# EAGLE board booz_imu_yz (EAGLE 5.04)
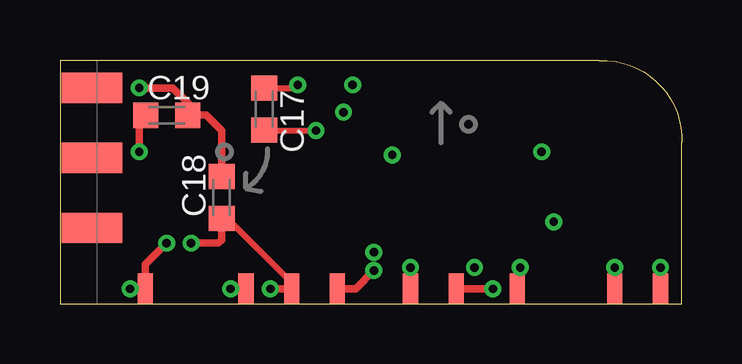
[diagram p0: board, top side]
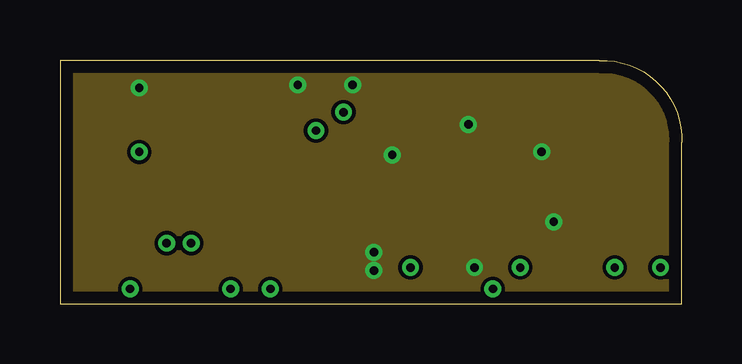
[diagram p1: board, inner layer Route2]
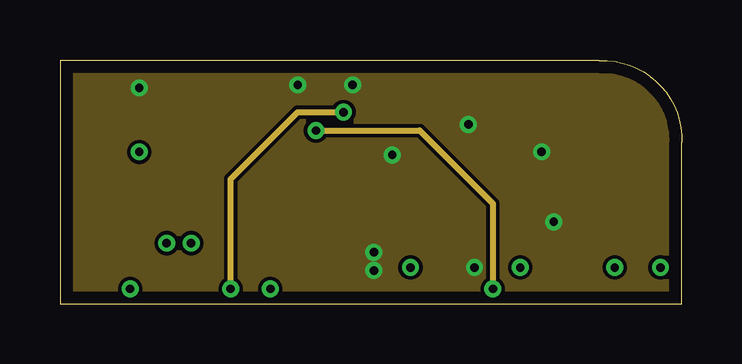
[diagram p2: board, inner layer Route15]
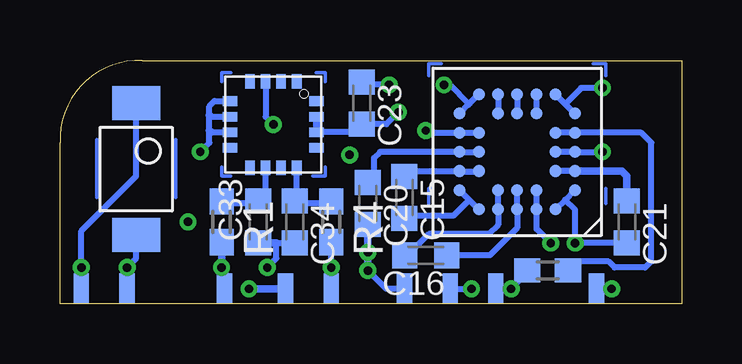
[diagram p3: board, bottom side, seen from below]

Size 25.91 x 10.16 mm. Coordinates in mm from the lower left corner, seen from the top.
Outline: 0,0 25.91,0 25.91,6.73 arc95 22.48,10.16 0,10.16 0,0
Copper layers (1*2+15*16): Top 0.035mm / dielectric 0.2mm / Route2 0.035mm / dielectric 1.5mm / Route15 0.035mm / dielectric 0.2mm / Bottom 0.035mm
Design rules "eurocircuits_verified_4l": minimum track width 0.15mm, minimum drill 0.35mm, track to track 0.15mm, track to pad 0.15mm, pad to pad 0.15mm, via to via 0.15mm, smd to smd 0.15mm, copper to edge 20mil, drill to drill 8mil, minimum pad ring 0.177mm, minimum via ring 0.177mm, stop-mask expansion 4mil, vias tented up to drill 14mil, thermal gap 10mil

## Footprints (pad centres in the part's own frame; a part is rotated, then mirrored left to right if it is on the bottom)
C0603K = smd 1.05 x 1.08: 1 -0.875,0; 2 0.875,0
BC-32 = smd 0.5 x 0.5: A2 -1.6,2.4; A3 -0.8,2.4; A4 0,2.4; A5 0.8,2.4; A6 1.6,2.4; B1 -2.4,1.6; B3 -0.8,1.6; B4 0,1.6; B5 0.8,1.6; B7 2.4,1.6; C1 -2.4,0.8; C2 -1.6,0.8; C6 1.6,0.8; C7 2.4,0.8; D1 -2.4,0; D2 -1.6,0; D6 1.6,0; D7 2.4,0; E1 -2.4,-0.8; E2 -1.6,-0.8; E6 1.6,-0.8; E7 2.4,-0.8; F1 -2.4,-1.6; F3 -0.8,-1.6; F4 0,-1.6; F5 0.8,-1.6; F7 2.4,-1.6; G2 -1.6,-2.4; G3 -0.8,-2.4; G4 0,-2.4; G5 0.8,-2.4; G6 1.6,-2.4
R0603 = smd 1.1 x 1: 1 -0.85,0; 2 0.85,0
SOLDER_PAD = smd 0.635 x 1.27: P$1 0,0
LSCFP = smd 0.6 x 0.4: P$1 -1.8,0.975; P$2 -1.8,0.325; P$3 -1.8,-0.325; P$4 -1.8,-0.975; P$9 1.8,-0.975; P$10 1.8,-0.325; P$11 1.8,0.325; P$12 1.8,0.975 | smd 0.4 x 0.6: P$5 -0.975,-1.8; P$6 -0.325,-1.8; P$7 0.325,-1.8; P$8 0.975,-1.8; P$13 0.975,1.8; P$14 0.325,1.8; P$15 -0.325,1.8; P$16 -0.975,1.8
SEN_XY = smd 1.4 x 2: P$1 0,0; P$2 5.5,0

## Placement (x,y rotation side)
C15  22nF  [C0603K]  11.56,4.45 270 bottom
C16  22nF  [C0603K]  10.67,2.03 180 bottom
C17  100nF  [C0603K]  8.51,8.13 270 top
C18  100nF  [C0603K]  6.73,4.45 90 top
C19  100nF  [C0603K]  4.45,7.87 0 top
C20  47nF  [C0603K]  13.08,4.19 270 bottom
C21  22nF  [C0603K]  2.29,3.43 270 bottom
C23  100nF  [C0603K]  13.33,8.38 270 bottom
C33  100nF  [C0603K]  17.65,3.43 90 bottom
C34  100nF  [C0603K]  16.13,3.43 270 bottom
GYRO_X  ADXR  [BC-32]  6.86,6.35 180 bottom
R1  12k  [R0603]  19.18,3.43 270 bottom
R4  12k  [R0603]  14.6,3.43 270 bottom
R5  0/DNP  [R0603]  5.59,1.4 0 bottom
U$1  SOLDER_PAD  [SOLDER_PAD]  19.05,0.64 0 top
U$2  ADXL320  [LSCFP]  17.02,7.49 270 bottom
U$3  SOLDER_PAD  [SOLDER_PAD]  1.65,9.02 0 top
U$4  SOLDER_PAD  [SOLDER_PAD]  14.6,0.64 0 top
U$5  SOLDER_PAD  [SOLDER_PAD]  3.56,0.64 0 top
U$6  SOLDER_PAD  [SOLDER_PAD]  9.65,0.64 0 top
U$7  SOLDER_PAD  [SOLDER_PAD]  16.51,0.64 0 top
U$8  SOLDER_PAD  [SOLDER_PAD]  11.56,0.64 0 top
U$9  SEN_XY  [SEN_XY]  22.73,8.38 270 bottom
U$10  SOLDER_PAD  [SOLDER_PAD]  1.65,6.1 0 top
U$11  SOLDER_PAD  [SOLDER_PAD]  1.65,3.17 0 top
U$12  SOLDER_PAD  [SOLDER_PAD]  23.11,0.64 0 top
U$13  SOLDER_PAD  [SOLDER_PAD]  25.02,0.64 0 top
U$14  SOLDER_PAD  [SOLDER_PAD]  11.56,0.64 0 bottom
U$15  SOLDER_PAD  [SOLDER_PAD]  16.51,0.64 0 bottom
U$16  SOLDER_PAD  [SOLDER_PAD]  9.65,0.64 0 bottom
U$17  SOLDER_PAD  [SOLDER_PAD]  25.02,0.64 0 bottom
U$18  SOLDER_PAD  [SOLDER_PAD]  23.11,0.64 0 bottom
U$19  SOLDER_PAD  [SOLDER_PAD]  14.6,0.64 0 bottom
U$20  SOLDER_PAD  [SOLDER_PAD]  19.05,0.64 0 bottom
U$21  SOLDER_PAD  [SOLDER_PAD]  3.56,0.64 0 bottom
U$22  SOLDER_PAD  [SOLDER_PAD]  1.02,9.02 0 top
U$23  SOLDER_PAD  [SOLDER_PAD]  1.02,6.1 0 top
U$24  SOLDER_PAD  [SOLDER_PAD]  7.75,0.64 0 bottom
U$25  SOLDER_PAD  [SOLDER_PAD]  7.75,0.64 0 top
U$26  SOLDER_PAD  [SOLDER_PAD]  2.29,9.02 0 top
U$27  SOLDER_PAD  [SOLDER_PAD]  2.29,6.1 0 top
U$28  SOLDER_PAD  [SOLDER_PAD]  2.29,3.17 0 top
U$29  SOLDER_PAD  [SOLDER_PAD]  1.02,3.17 0 top
U$30  SOLDER_PAD  [SOLDER_PAD]  0.38,9.02 0 top
U$31  SOLDER_PAD  [SOLDER_PAD]  0.38,6.1 0 top
U$32  SOLDER_PAD  [SOLDER_PAD]  0.38,3.17 0 top

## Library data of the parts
C15-C21 C23 C33 C34 R1 R4 R5 = rcl
GYRO_X U$1-U$8 U$10-U$32 = paparazzi
U$9 = booz

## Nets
+5V: C17.2 GYRO_X.E6 GYRO_X.E7 U$7.P$1 U$15.P$1
+5VA: C18.1 GYRO_X.A3 GYRO_X.B3 U$6.P$1 U$16.P$1
ACCEL_H: R4.2 U$4.P$1 U$19.P$1
ACCEL_V: R1.2 U$1.P$1 U$20.P$1
GND: C17.1 C18.2 C19.2 C20.2 C23.1 C33.1 C34.2 GYRO_X.F1 GYRO_X.F7 GYRO_X.G2 GYRO_X.G6 U$2.P$3 U$2.P$5 U$2.P$6 U$2.P$7 U$8.P$1 U$14.P$1
MAG_N: U$9.P$2 U$12.P$1 U$18.P$1
MAG_P: U$9.P$1 U$13.P$1 U$17.P$1
N$6: C21.1 GYRO_X.C1 GYRO_X.C2
N$7: C15.1 GYRO_X.C6 GYRO_X.C7
N$11: C20.1 GYRO_X.D6 GYRO_X.D7
N$12: C16.2 GYRO_X.A5 GYRO_X.B5
N$13: C16.1 GYRO_X.A4 GYRO_X.B4
N$14: C15.2 GYRO_X.A6 GYRO_X.B7
N$19: C19.1 GYRO_X.D1 GYRO_X.D2
N$20: C33.2 R1.1 U$2.P$10
N$32: C34.1 R4.1 U$2.P$12
RATE_X: C21.2 GYRO_X.A2 GYRO_X.B1 U$5.P$1 U$21.P$1
ST1: GYRO_X.F5 GYRO_X.G5
ST2: GYRO_X.F4 GYRO_X.G4
TEMP_X: GYRO_X.F3 GYRO_X.G3
VRATIO_OR_2V5: GYRO_X.E1 GYRO_X.E2 R5.2
VREF: C23.2 R5.1 U$2.P$14 U$2.P$15 U$24.P$1 U$25.P$1

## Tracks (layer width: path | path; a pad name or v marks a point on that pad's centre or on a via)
+5V  (via drill 0.35)
  Top 0.254: C17.2 8.51,7.24 v10.67,7.24
  Top 0.305: v18.03,0.64 U$15.P$1
  Route15 0.254: v18.03,0.64 18.03,4.19 14.99,7.24 v10.67,7.24
  Bottom 0.203: 9.25,7.16 GYRO_X.E7 | GYRO_X.E6
  Bottom 0.254: 9.25,7.16 GYRO_X.E6 | GYRO_X.E7 10.58,7.15 v10.67,7.24
  Bottom 0.305: v18.03,0.64 U$15.P$1 | 8.41,7.14 8.42,7.15 GYRO_X.E6
+5VA  (via drill 0.35)
  Top 0.254: 6.73,3.56 6.98,3.56 9.65,0.89 U$16.P$1
  Top 0.305: v8.76,0.64 U$16.P$1 | v5.46,2.54 6.6,2.54 6.73,2.67 6.73,3.56 C18.1
  Bottom 0.203: 6.04,3.96 6.05,3.96 GYRO_X.A3 | 6.04,4.74 GYRO_X.B3
  Bottom 0.254: 6.04,4.74 6.04,3.96 6.04,3.12 v5.46,2.54 | U$16.P$1 v8.76,0.64
ACCEL_H  (via drill 0.35)
  Top 0.305: v14.6,1.52 U$19.P$1
  Bottom 0.254: v14.6,1.52 R4.2
  Bottom 0.305: U$19.P$1 v14.6,1.52
ACCEL_V  (via drill 0.35)
  Top 0.305: v19.18,1.52 19.05,1.27 U$20.P$1
  Bottom 0.305: R1.2 v19.18,1.52 19.05,1.4 U$20.P$1
GND  (via drill 0.35)
  Top 0.254: C17.1 9.77,9 v9.91,9.14
  Top 0.305: v3.3,9.02 4.7,9.02 5.33,8.38 5.33,7.87 6.1,7.87 6.73,7.24 C18.2 | U$14.P$1 12.32,0.64 v13.08,1.4 | C17.1 8.51,9.02 8.89,9.02
  Top 0.406: 5.33,7.87 C19.2
  Bottom 0.203: GYRO_X.F7 9.25,7.96 9.25,7.98 9.23,7.98 | GYRO_X.G2 5.26,8.74 5.25,8.74 | GYRO_X.G2
  Bottom 0.254: 4.86,8.35 5.25,8.74 | 4.86,8.35 GYRO_X.F1 | C34.2 16.89,2.55 16.89,1.91 v17.27,1.52 | v3.3,9.02 4.19,9.02 4.86,8.35 | v13.08,1.4 12.32,0.64 U$14.P$1 | U$2.P$5 19.47,8.47 19.69,8.25 19.69,7.87 19.69,7.24 19.69,6.73 v20.07,6.35 | 19.61,7.17 U$2.P$7 | 19.63,7.82 U$2.P$6 | U$2.P$3 17.34,7.82 v17.02,7.49 | v12.19,9.14 13.33,9.14 | GYRO_X.G6 8.83,8.38 8.89,8.38 | GYRO_X.F7 8.89,8.32 8.89,8.38 | 8.89,8.38 9.65,9.14 v9.91,9.14
  Bottom 0.305: 16.89,2.55 C33.1 | GYRO_X.F7 9.27,7.96 9.27,8 9.21,8 | v13.08,1.4 v13.08,2.16 C20.2 | 19.69,7.24 19.61,7.17 | 19.69,7.87 19.63,7.82 | 13.33,9.14 C23.1
  other vias: 13.84,6.22 20.57,3.43
  pour Route2: -0.25,10.03 25.78,10.03 25.78,0.13 -0.25,0.13
  pour Route15: -0.25,10.03 25.78,10.03 25.78,0.13 -0.25,0.13
MAG_N  (via drill 0.35)
  Top 0.254: v23.11,1.52 U$18.P$1
  Bottom 0.254: U$18.P$1 v23.11,1.52 22.73,1.91 U$9.P$2 22.73,2.92
MAG_P  (via drill 0.35)
  Top 0.254: v25.02,1.52 U$17.P$1
  Bottom 0.254: U$17.P$1 v25.02,1.52 25.02,3.05 22.73,5.33 U$9.P$1
N$1
  Bottom 0.152: 3.18,4.19 3.18,4.83
N$2
  Bottom 0.152: 10.03,10.03 10.54,10.03 10.54,9.52
N$3
  Bottom 0.152: 3.68,10.03 3.18,10.03 3.18,9.52
N$4
  Bottom 0.152: 10.54,4.19 10.54,4.83
N$5
  Bottom 0.152: 15.24,9.65 14.86,9.65 14.86,9.27
N$6
  Bottom 0.203: GYRO_X.C2 | GYRO_X.C2 5.26,5.56
  Bottom 0.254: GYRO_X.C1 GYRO_X.C2 | C21.1 2.29,4.19
  Bottom 0.305: GYRO_X.C1 2.5,5.55 2.29,5.33 C21.1
N$7
  Bottom 0.203: 9.27,5.54 | GYRO_X.C7 9.27,5.54 | GYRO_X.C6
  Bottom 0.254: GYRO_X.C6 9.27,5.54 10.34,5.54 11.35,5.54 C15.1
N$8
  Bottom 0.152: 18.8,9.65 19.18,9.65 19.18,9.27
N$9
  Bottom 0.152: 19.18,5.72 19.18,5.33 18.8,5.33
N$10
  Bottom 0.152: 15.37,5.33 14.86,5.33 14.86,5.72
N$11
  Bottom 0.254: GYRO_X.D6 GYRO_X.D7 12.06,6.35 12.57,6.35 12.83,6.1 12.83,5.33 13.08,5.08
  Bottom 0.305: C20.1 13.08,5.08 13.08,5.33
N$12
  Bottom 0.203: 7.64,3.94 | GYRO_X.A5 7.64,3.94 | 7.64,4.74 GYRO_X.B5
  Bottom 0.254: 7.64,3.94 7.64,4.74 | GYRO_X.A5 7.66,3.3 8.04,2.92 9.02,2.92 10.54,2.92 11.43,2.03 C16.2
N$13
  Bottom 0.254: GYRO_X.B4 GYRO_X.A4 6.86,3.17 8,2.03 C16.1
N$14
  Bottom 0.203: GYRO_X.B7 9.25,4.75 9.25,4.74 | GYRO_X.B7
  Bottom 0.254: GYRO_X.A6 8.86,4.35 | 8.86,4.35 9.25,4.74 | 8.86,4.35 9.53,3.68 11.44,3.68 C15.2 11.56,3.43 11.54,3.43
N$15
  Bottom 0.152: 21.08,4.45 21.08,6.86
N$16
  Bottom 0.152: 24.38,4.45 24.38,6.86
N$19  (via drill 0.35)
  Top 0.305: C19.1 3.56,7.87 3.68,7.87 3.3,7.49 v3.3,6.35
  Bottom 0.254: GYRO_X.D2 GYRO_X.D1 v3.3,6.35
N$20
  Bottom 0.254: C33.2 17.65,4.19 19.3,4.19 19.18,4.32 R1.1 | 17.34,4.45 U$2.P$10
  Bottom 0.305: 17.65,4.32 C33.2 17.65,4.45 17.34,4.45
N$32
  Bottom 0.254: C34.1 16.13,4.19 16.09,4.15 16,4.15 15.87,4.15 | 14.6,4.19 15.84,4.19 | 16.04,4.19 U$2.P$12
  Bottom 0.305: 15.92,4.23 15.87,4.19 15.87,4.15 15.84,4.19 | R4.1 14.6,4.19 | 16,4.15 16,4.19 16.04,4.19
RATE_X  (via drill 0.35)
  Top 0.254: U$21.P$1 v2.92,0.64
  Top 0.305: U$21.P$1 3.56,1.65 v4.45,2.54
  Bottom 0.203: GYRO_X.A2 5.27,3.94 5.28,3.94
  Bottom 0.254: v2.92,0.64 U$21.P$1 | 4.86,4.35 GYRO_X.B1 | 4.86,4.35 5.27,3.94 | 2.29,2.54 v4.45,2.54 4.45,3.94 4.86,4.35
  Bottom 0.305: C21.2 2.29,2.54
ST1
  Bottom 0.203: 7.64,7.95 GYRO_X.F5 | GYRO_X.F5 | GYRO_X.G5 7.64,8.74
  Bottom 0.254: 7.64,8.74 7.64,7.95
ST2
  Bottom 0.254: GYRO_X.G4 GYRO_X.F4
TEMP_X
  Bottom 0.203: GYRO_X.F3 | GYRO_X.F3 | GYRO_X.G3 6.07,8.74
  Bottom 0.254: 6.07,8.74 GYRO_X.F3
VRATIO_OR_2V5
  Bottom 0.254: R5.2 4.74,1.36 4.32,1.78 3.05,1.78 2.79,1.52 1.52,1.52 1.27,1.78 1.27,6.73 1.69,7.15 GYRO_X.E1 4.46,7.13 | 4.46,7.13 4.45,7.11 | GYRO_X.E2 4.48,7.15 4.46,7.13
VREF  (via drill 0.35)
  Top 0.305: v7.11,0.64 U$25.P$1
  Route15 0.254: v7.11,0.64 7.11,5.21 9.91,8 v11.81,8
  Bottom 0.254: U$25.P$1 v7.11,0.64 6.48,1.27 R5.1 | U$2.P$14 15.22,7.13 15.24,7.11 | 13.33,7.17 15.17,7.17 | C23.2 12.31,7.51 v11.81,8
  Bottom 0.305: C23.2 13.33,7.37 | 13.33,7.37 13.21,7.24 | U$2.P$14 15.17,7.17 15.22,7.22 15.22,7.73 15.24,7.75 15.22,7.77 U$2.P$15 | 13.33,7.37 13.33,7.17

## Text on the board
tDocu: q | Az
